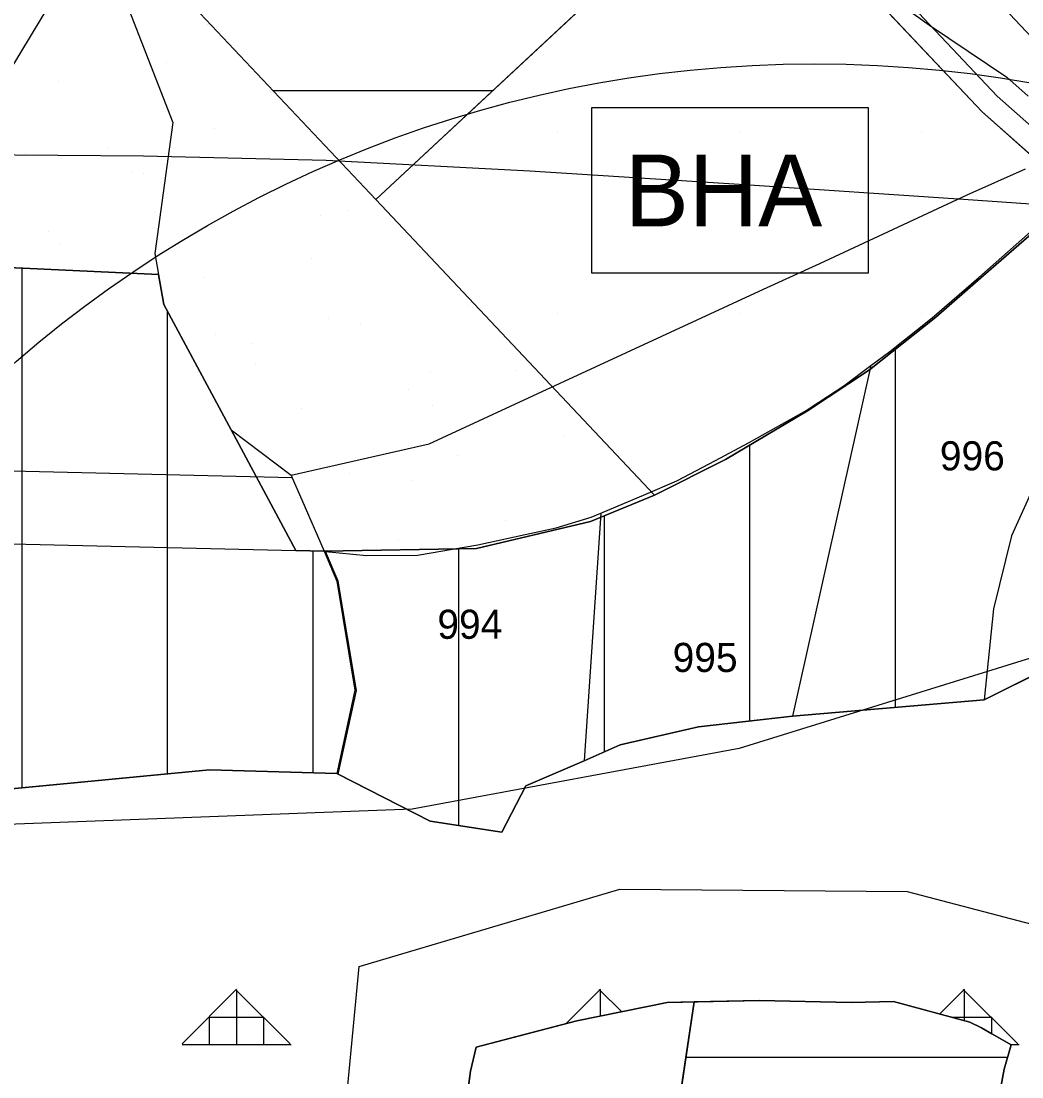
# Model space of a CAD drawing. Extents: x 410727 to 412947, y 4463506 to 4466382.
# Drawn here: x 411364.1 to 411501.6, y 4465781.8 to 4465926.9 of the extents above; entities that cross this region are included whole.
import ezdxf

# ---------------------------------------------------------------- set-up
doc = ezdxf.new("R2010")
doc.units = 0
for name, color, linetype in [('ADAKENARI', 7, 'Continuous'), ('KALDIRIM', 7, 'Continuous'), ('KDS_PARSEL_NO', 7, 'Continuous'), ('KDS_PL', 7, 'Continuous'), ('LJ_ÇERÇEVE', 7, 'Continuous'), ('PL_AYA_ORMAN', 7, 'Continuous'), ('PL_AYA_PARK_DINLENME', 7, 'Continuous'), ('PL_GELİŞME_KONUT', 7, 'Continuous'), ('PL_K_BHA', 7, 'Continuous'), ('PL_KON_MEV_050', 7, 'Continuous'), ('PL_KON_ONE_50', 7, 'Continuous'), ('sembol', 7, 'Continuous'), ('SN_ONAMA', 7, 'Continuous'), ('TR_AZYOGUNLUK_MESKUN', 7, 'Continuous'), ('TR_GELİŞME_KONUT_ÇOKAZ', 7, 'Continuous'), ('TR_ORMAN', 7, 'Continuous'), ('TR_PARKALANI', 7, 'Continuous'), ('TR_SU_DEPOSU', 7, 'Continuous'), ('Yerlesime_uygunluk_sınırı', 7, 'Continuous')]:
    doc.layers.add(name, color=color, linetype=linetype)

msp = doc.modelspace()

# ---------------------------------------------------------------- linework, layer by layer
at = {"layer": 'ADAKENARI'}
for p, q in [((411412.85, 4465902.41), (411463.26, 4465949.34)), ((411463.26, 4465949.34), (411496.15, 4465914.44)), ((411496.15, 4465914.44), (411508.68, 4465903.34)), ((411451.16, 4465861.77), (411412.85, 4465902.41)), ((411496.33, 4465891.98), (411503.64, 4465898.27)), ((411309.34, 4465895.53), (411383, 4465892.12)), ((411383, 4465892.12), (411383.75, 4465887.97)), ((411489.78, 4465886.25), (411496.33, 4465891.98)), ((411383.75, 4465887.97), (411393, 4465870.75)), ((411480.69, 4465879.01), (411489.78, 4465886.25)), ((411472.17, 4465873.35), (411480.69, 4465879.01)), ((411460.91, 4465866.67), (411472.17, 4465873.35)), ((411393, 4465870.75), (411401.9, 4465854.15)), ((411451.16, 4465861.77), (411460.91, 4465866.67)), ((411451.16, 4465861.77), (411442.37, 4465858.17)), ((411426.7, 4465854.46), (411442.37, 4465858.17)), ((411405.75, 4465854.06), (411401.9, 4465854.15)), ((411405.75, 4465854.06), (411426.7, 4465854.46)), ((411496.44, 4465833.66), (411538.79, 4465854.78)), ((411496.44, 4465833.66), (411470.13, 4465831.39)), ((411470.13, 4465831.39), (411457.2, 4465829.93)), ((411457.2, 4465829.93), (411446.43, 4465827.44)), ((411446.43, 4465827.44), (411441.48, 4465825.25)), ((411441.48, 4465825.25), (411433.46, 4465821.81)), ((411337.5, 4465818.97), (411390, 4465824)), ((411390, 4465824), (411407.51, 4465823.5)), ((411420.35, 4465816.97), (411407.51, 4465823.5)), ((411433.46, 4465821.81), (411430.18, 4465815.46)), ((411430.18, 4465815.46), (411420.35, 4465816.97)), ((411456.62, 4465792.14), (411445.98, 4465721.04))]:
    msp.add_line(p, q, dxfattribs=at)
for points in [[(411325.67, 4466003.81), (411366.7, 4465995.24), (411399.69, 4465991.77), (411415.6, 4465986.82), (411440.85, 4465973.12), (411463.26, 4465949.34), (411412.85, 4465902.41), (411380.18, 4465937.08), (411373.01, 4465940.76), (411281.5, 4465952.98)], [(411281.5, 4465952.98), (411373.01, 4465940.76), (411380.18, 4465937.08), (411412.85, 4465902.41), (411451.16, 4465861.77), (411442.37, 4465858.17), (411426.7, 4465854.46), (411405.75, 4465854.06), (411401.9, 4465854.15), (411393, 4465870.75), (411383.75, 4465887.97), (411383, 4465892.12), (411309.34, 4465895.53)], [(411424.6, 4465772.83), (411425.86, 4465782.59), (411426.64, 4465785.89), (411433.96, 4465787.81), (411440.46, 4465789.51), (411452.87, 4465792.03), (411465.59, 4465792.34), (411478.16, 4465792.03), (411483.97, 4465792.19), (411494.49, 4465789.35), (411496.06, 4465788.57), (411497.5, 4465787.74), (411500.15, 4465786.21), (411499.2, 4465782.9), (411498.42, 4465778.65)]]:
    msp.add_lwpolyline(points, dxfattribs=at)
at = {"layer": 'KALDIRIM'}
for points in [[(411363.84, 4466008.09), (411368.56, 4466007.11), (411402.12, 4466003.58), (411420.29, 4465997.93), (411448.26, 4465982.75), (411504.51, 4465923.06), (411515.54, 4465913.29), (411544.92, 4465897.92), (411576.35, 4465881.49), (411596.27, 4465871.64)], [(411592.71, 4465863.36), (411572.27, 4465873.46), (411540.75, 4465889.95), (411510.4, 4465905.83), (411498.24, 4465916.59), (411442.7, 4465975.53), (411416.77, 4465989.6), (411400.3, 4465994.72)]]:
    msp.add_lwpolyline(points, dxfattribs=at)
at = {"layer": 'KDS_PL'}
for p, q in [((411362.5, 4465919.97), (411374.5, 4465940)), ((411374.5, 4465940), (411385, 4465913)), ((411480.94, 4465932.11), (411488.93, 4465926.36)), ((411488.93, 4465926.36), (411499.54, 4465919.22)), ((411499.54, 4465919.22), (411502.49, 4465916.61)), ((411385, 4465913), (411382.5, 4465895)), ((411494.1, 4465903.04), (411502.12, 4465906.61)), ((411473.88, 4465893.63), (411494.1, 4465903.04)), ((411495.72, 4465891.7), (411502.79, 4465897.97)), ((411309.34, 4465895.53), (411383, 4465892.12)), ((411382.5, 4465895), (411383, 4465892.12)), ((411466.13, 4465890.07), (411473.88, 4465893.63)), ((411383, 4465892.12), (411383.75, 4465887.97)), ((411489.28, 4465886.15), (411495.72, 4465891.7)), ((411438.21, 4465877.16), (411466.13, 4465890.07)), ((411383.75, 4465887.97), (411393, 4465870.75)), ((411483.49, 4465881.52), (411489.28, 4465886.15)), ((411480.89, 4465879.59), (411483.49, 4465881.52)), ((411480.89, 4465879.59), (411470.13, 4465831.39)), ((411477.16, 4465876.8), (411480.89, 4465879.59)), ((411420.21, 4465868.83), (411438.21, 4465877.16)), ((411472.68, 4465873.85), (411477.16, 4465876.8)), ((411472.07, 4465873.44), (411472.68, 4465873.85)), ((411464.06, 4465868.96), (411472.07, 4465873.44)), ((411393, 4465870.75), (411401.25, 4465864.5)), ((411401.25, 4465864.5), (411420.21, 4465868.83)), ((411459.53, 4465866.52), (411464.06, 4465868.96)), ((411454.2, 4465863.75), (411459.53, 4465866.52)), ((411401.38, 4465864.16), (411343.25, 4465865.53)), ((411401.25, 4465864.5), (411401.38, 4465864.16)), ((411401.38, 4465864.16), (411402.69, 4465861.12)), ((411449.97, 4465861.89), (411454.2, 4465863.75)), ((411503.89, 4465864.4), (411500.21, 4465856.16)), ((411402.69, 4465861.12), (411405.75, 4465854.06)), ((411443.78, 4465859.29), (411449.97, 4465861.89)), ((411443.79, 4465859.3), (411441.49, 4465825.25)), ((411442.43, 4465858.73), (411443.79, 4465859.3)), ((411437.66, 4465857.29), (411442.43, 4465858.73)), ((411433.4, 4465856.35), (411437.66, 4465857.29)), ((411342.62, 4465855.53), (411405.75, 4465854.06)), ((411418.61, 4465853.53), (411426.88, 4465854.93)), ((411426.88, 4465854.93), (411433.4, 4465856.35)), ((411500.21, 4465856.16), (411497.7, 4465846.17)), ((411405.75, 4465854.06), (411407.5, 4465849.97)), ((411405.94, 4465854.02), (411411.57, 4465853.47)), ((411407.7, 4465849.93), (411405.94, 4465854.02)), ((411411.57, 4465853.47), (411418.61, 4465853.53)), ((411538.79, 4465854.78), (411496.44, 4465833.66)), ((411407.5, 4465849.97), (411410, 4465834.97)), ((411410.19, 4465834.91), (411407.7, 4465849.93)), ((411497.7, 4465846.17), (411496.44, 4465833.66)), ((411410, 4465834.97), (411407.5, 4465823.5)), ((411407.69, 4465823.41), (411410.19, 4465834.91)), ((411496.44, 4465833.66), (411470.13, 4465831.39)), ((411470.13, 4465831.39), (411457.2, 4465829.93)), ((411457.2, 4465829.93), (411446.43, 4465827.44)), ((411446.43, 4465827.44), (411441.48, 4465825.25)), ((411441.49, 4465825.25), (411439.18, 4465824.23)), ((411390, 4465824), (411337.5, 4465818.97)), ((411407.5, 4465823.5), (411390, 4465824)), ((411420.35, 4465816.97), (411407.69, 4465823.41)), ((411439.18, 4465824.23), (411433.46, 4465821.81)), ((411433.46, 4465821.81), (411430.18, 4465815.46)), ((411430.18, 4465815.46), (411420.35, 4465816.97)), ((411440.46, 4465789.51), (411452.87, 4465792.03)), ((411452.87, 4465792.03), (411465.59, 4465792.34)), ((411465.59, 4465792.34), (411478.16, 4465792.03)), ((411483.97, 4465792.19), (411478.16, 4465792.03)), ((411494.49, 4465789.35), (411483.97, 4465792.19)), ((411426.64, 4465785.89), (411440.46, 4465789.51)), ((411496.06, 4465788.57), (411494.49, 4465789.35)), ((411500.15, 4465786.21), (411496.06, 4465788.57)), ((411425.86, 4465782.59), (411426.64, 4465785.89)), ((411499.2, 4465782.9), (411500.15, 4465786.21)), ((411424.6, 4465772.83), (411425.86, 4465782.59)), ((411498.42, 4465778.65), (411499.2, 4465782.9))]:
    msp.add_line(p, q, dxfattribs=at)
at = {"layer": 'LJ_ÇERÇEVE'}
msp.add_circle((411473.17, 4465753.45), 167.6, dxfattribs=at)
at = {"layer": 'PL_AYA_ORMAN'}
for points in [[(411598.22, 4465856.51), (411570.91, 4465870.79), (411538.79, 4465854.78), (411496.44, 4465833.66), (411470.13, 4465831.39), (411457.2, 4465829.93), (411446.43, 4465827.44), (411441.48, 4465825.25), (411433.46, 4465821.81), (411430.18, 4465815.46), (411420.35, 4465816.97), (411407.51, 4465823.5), (411390, 4465824), (411337.5, 4465818.97)], [(411424.6, 4465772.83), (411425.86, 4465782.59), (411426.64, 4465785.89), (411440.46, 4465789.51), (411452.87, 4465792.03), (411465.59, 4465792.34), (411478.16, 4465792.03), (411483.97, 4465792.19), (411494.49, 4465789.35), (411496.06, 4465788.57), (411500.15, 4465786.21), (411499.2, 4465782.9), (411498.42, 4465778.65)]]:
    msp.add_lwpolyline(points, dxfattribs=at)
at = {"layer": 'PL_AYA_PARK_DINLENME'}
msp.add_lwpolyline([(411309.34, 4465895.53), (411383, 4465892.12), (411383.75, 4465887.97), (411393, 4465870.75), (411401.9, 4465854.15), (411405.75, 4465854.06), (411426.7, 4465854.46), (411442.37, 4465858.17), (411451.16, 4465861.77), (411412.85, 4465902.41), (411380.18, 4465937.08), (411373.01, 4465940.76), (411281.5, 4465952.98)], dxfattribs=at)
at = {"layer": 'PL_GELİŞME_KONUT'}
msp.add_lwpolyline([(411454.07, 4465719.35), (411454.07, 4465719.35), (411487.47, 4465711.77), (411488.52, 4465720.11), (411493.07, 4465740.04), (411493.07, 4465740.06), (411493.08, 4465740.1), (411496.22, 4465754.58), (411496.85, 4465761.03), (411497.95, 4465772.2), (411498.42, 4465778.65), (411499.2, 4465782.9), (411500.15, 4465786.21), (411497.5, 4465787.74), (411496.06, 4465788.57), (411494.49, 4465789.35), (411483.97, 4465792.19), (411478.16, 4465792.03), (411465.59, 4465792.34), (411456.62, 4465792.12), (411445.98, 4465721.04), (411445.98, 4465721.04)], dxfattribs=at)
at = {"layer": 'PL_K_BHA'}
for points in [[(411412.85, 4465902.41), (411451.16, 4465861.77), (411460.91, 4465866.67), (411472.17, 4465873.35), (411480.69, 4465879.01), (411489.78, 4465886.25), (411496.33, 4465891.98), (411503.64, 4465898.27), (411508.68, 4465903.34), (411496.15, 4465914.44), (411463.26, 4465949.34), (411412.85, 4465902.41)], [(411445.98, 4465721.04), (411456.62, 4465792.12), (411452.87, 4465792.03), (411440.46, 4465789.51), (411433.96, 4465787.81), (411426.64, 4465785.89), (411425.86, 4465782.59), (411424.6, 4465772.83), (411423.19, 4465756.15), (411419.73, 4465742.46), (411416.28, 4465732.86), (411412.98, 4465728.93), (411410.34, 4465725.3), (411410.34, 4465725.3)]]:
    msp.add_lwpolyline(points, dxfattribs=at)
at = {"layer": 'PL_KON_MEV_050'}
for points in [[(411503.64, 4465898.27), (411496.33, 4465891.98), (411489.78, 4465886.25), (411480.69, 4465879.01), (411472.17, 4465873.35), (411460.91, 4465866.67), (411451.16, 4465861.77), (411442.37, 4465858.17), (411426.7, 4465854.46), (411405.75, 4465854.06), (411401.9, 4465854.15), (411393, 4465870.75), (411383.75, 4465887.97), (411383, 4465892.12), (411309.34, 4465895.53)], [(411337.5, 4465818.97), (411390, 4465824), (411407.51, 4465823.5), (411420.35, 4465816.97), (411430.18, 4465815.46), (411433.46, 4465821.81), (411441.48, 4465825.25), (411446.43, 4465827.44), (411457.2, 4465829.93), (411470.13, 4465831.39), (411496.44, 4465833.66), (411538.79, 4465854.78)]]:
    msp.add_lwpolyline(points, dxfattribs=at)
at = {"layer": 'PL_KON_ONE_50'}
msp.add_lwpolyline([(411281.5, 4465952.98), (411373.01, 4465940.76), (411380.18, 4465937.08), (411412.85, 4465902.41), (411463.26, 4465949.34), (411440.85, 4465973.12), (411415.6, 4465986.82), (411399.69, 4465991.77), (411366.7, 4465995.24), (411325.67, 4466003.81)], dxfattribs=at)
at = {"layer": 'sembol'}
for p, q in [((411442.55, 4465892.27), (411442.55, 4465915.05)), ((411442.55, 4465915.05), (411480.51, 4465915.05)), ((411480.51, 4465915.05), (411480.51, 4465892.27)), ((411480.51, 4465892.27), (411442.55, 4465892.27))]:
    msp.add_line(p, q, dxfattribs=at)
at = {"layer": 'SN_ONAMA'}
msp.add_lwpolyline([(411383.47, 4465701.98), (411406.89, 4465758.05), (411410.6, 4465797.01), (411446.38, 4465807.63), (411485.88, 4465807.28), (411522.02, 4465797.82), (411500.54, 4465684.33), (411414.88, 4465701.98)], close=True, dxfattribs=at)
at = {"layer": 'TR_AZYOGUNLUK_MESKUN'}
for p, q in [((411364.26, 4465821.53), (411364.26, 4465892.99)), ((411384.26, 4465823.45), (411384.26, 4465887.02)), ((411484.26, 4465832.61), (411484.26, 4465881.85)), ((411464.26, 4465830.73), (411464.26, 4465868.66)), ((411444.26, 4465826.48), (411444.26, 4465858.94)), ((411404.26, 4465823.59), (411404.26, 4465854.09)), ((411424.26, 4465816.37), (411424.26, 4465854.41))]:
    msp.add_line(p, q, dxfattribs=at)
at = {"layer": 'TR_GELİŞME_KONUT_ÇOKAZ'}
for p, q in [((411398.74, 4465917.39), (411428.94, 4465917.39)), ((411455.49, 4465784.54), (411499.51, 4465784.54))]:
    msp.add_line(p, q, dxfattribs=at)
msp.add_lwpolyline([(411281.5, 4465952.98), (411373.01, 4465940.76), (411380.18, 4465937.08), (411412.85, 4465902.41), (411463.26, 4465949.34), (411440.85, 4465973.12), (411415.6, 4465986.82), (411399.69, 4465991.77), (411366.7, 4465995.24), (411325.67, 4466003.81)], dxfattribs=at)
at = {"layer": 'TR_ORMAN'}
for p, q in [((411386.24, 4465786.37), (411393.74, 4465793.87)), ((411401.08, 4465786.34), (411393.58, 4465793.84)), ((411393.75, 4465786.29), (411393.75, 4465793.79)), ((411438.99, 4465789.12), (411443.74, 4465793.88)), ((411446.65, 4465790.77), (411443.57, 4465793.84)), ((411443.75, 4465790.18), (411443.75, 4465793.79)), ((411490.33, 4465790.47), (411493.74, 4465793.89)), ((411501.07, 4465786.34), (411493.57, 4465793.84)), ((411493.75, 4465789.55), (411493.75, 4465793.79)), ((411390, 4465786.29), (411390, 4465790.04)), ((411390, 4465790.04), (411397.5, 4465790.04)), ((411397.5, 4465786.29), (411397.5, 4465790.04)), ((411491.94, 4465790.04), (411497.5, 4465790.04)), ((411497.5, 4465787.74), (411497.5, 4465790.04)), ((411386.25, 4465786.29), (411401.25, 4465786.29)), ((411500, 4465786.29), (411501.25, 4465786.29))]:
    msp.add_line(p, q, dxfattribs=at)
at = {"layer": 'TR_PARKALANI'}
for p, q in [((411389.78, 4465926.43), (411389.78, 4465926.43)), ((411389.78, 4465926.43), (411389.78, 4465926.43)), ((411384.07, 4465921.17), (411384.07, 4465921.17)), ((411384.07, 4465921.17), (411384.07, 4465921.17)), ((411369.3, 4465918.57), (411369.3, 4465918.57)), ((411369.3, 4465918.57), (411369.3, 4465918.57)), ((411390.73, 4465912.19), (411390.73, 4465912.19)), ((411390.73, 4465912.19), (411390.73, 4465912.19)), ((411364.71, 4465908.71), (411364.71, 4465908.71)), ((411375.96, 4465909.59), (411375.96, 4465909.59)), ((411375.96, 4465909.59), (411375.96, 4465909.59)), ((411395.13, 4465908.42), (411395.13, 4465908.42)), ((411379.48, 4465906.1), (411379.48, 4465906.1)), ((411380.89, 4465905.92), (411380.89, 4465905.92)), ((411397.39, 4465903.21), (411397.39, 4465903.21)), ((411397.39, 4465903.21), (411397.39, 4465903.21)), ((411382.62, 4465900.61), (411382.62, 4465900.61)), ((411382.62, 4465900.61), (411382.62, 4465900.61)), ((411405.23, 4465900.24), (411405.23, 4465900.24)), ((411405.23, 4465900.24), (411405.23, 4465900.24)), ((411409.03, 4465900.89), (411409.03, 4465900.89)), ((411367.85, 4465898), (411367.85, 4465898)), ((411367.85, 4465898), (411367.85, 4465898)), ((411369.4, 4465896.28), (411369.4, 4465896.28)), ((411369.4, 4465896.28), (411369.4, 4465896.28)), ((411404.05, 4465894.23), (411404.05, 4465894.23)), ((411404.05, 4465894.23), (411404.05, 4465894.23)), ((411389.28, 4465891.63), (411389.28, 4465891.63)), ((411389.28, 4465891.63), (411389.28, 4465891.63)), ((411425.49, 4465887.86), (411425.49, 4465887.86)), ((411425.49, 4465887.86), (411425.49, 4465887.86)), ((411406.42, 4465886.12), (411406.42, 4465886.12)), ((411410.71, 4465885.25), (411410.71, 4465885.25)), ((411410.71, 4465885.25), (411410.71, 4465885.25)), ((411390.78, 4465883.8), (411390.78, 4465883.8)), ((411395.94, 4465882.65), (411395.94, 4465882.65)), ((411395.94, 4465882.65), (411395.94, 4465882.65)), ((411396.34, 4465879.72), (411396.34, 4465879.72)), ((411420.33, 4465878.59), (411420.33, 4465878.59)), ((411432.15, 4465878.88), (411432.15, 4465878.88)), ((411432.15, 4465878.88), (411432.15, 4465878.88)), ((411417.38, 4465876.27), (411417.38, 4465876.27)), ((411417.38, 4465876.27), (411417.38, 4465876.27)), ((411435.1, 4465875.99), (411435.1, 4465875.99)), ((411420.69, 4465874.04), (411420.69, 4465874.04)), ((411420.69, 4465874.04), (411420.69, 4465874.04)), ((411402.6, 4465873.67), (411402.6, 4465873.67)), ((411402.6, 4465873.67), (411402.6, 4465873.67)), ((411438.81, 4465869.9), (411438.81, 4465869.9)), ((411438.81, 4465869.9), (411438.81, 4465869.9)), ((411424.04, 4465867.29), (411424.04, 4465867.29)), ((411424.04, 4465867.29), (411424.04, 4465867.29)), ((411409.26, 4465864.69), (411409.26, 4465864.69)), ((411409.26, 4465864.69), (411409.26, 4465864.69)), ((411417.72, 4465863.82), (411417.72, 4465863.82)), ((411402.08, 4465861.5), (411402.08, 4465861.5)), ((411445.47, 4465860.92), (411445.47, 4465860.92)), ((411445.47, 4465860.92), (411445.47, 4465860.92)), ((411430.7, 4465858.31), (411430.7, 4465858.31)), ((411430.7, 4465858.31), (411430.7, 4465858.31)), ((411415.92, 4465855.71), (411415.92, 4465855.71)), ((411415.92, 4465855.71), (411415.92, 4465855.71)), ((411431.63, 4465856.29), (411431.63, 4465856.29))]:
    msp.add_line(p, q, dxfattribs=at)
at = {"layer": 'TR_SU_DEPOSU'}
for p, q in [((411437.85, 4465911.77), (411437.85, 4465911.77)), ((411462.85, 4465911.77), (411462.85, 4465911.77)), ((411487.85, 4465911.77), (411487.85, 4465911.77)), ((411437.85, 4465886.77), (411437.85, 4465886.77)), ((411462.85, 4465886.77), (411462.85, 4465886.77)), ((411487.85, 4465886.77), (411487.85, 4465886.77))]:
    msp.add_line(p, q, dxfattribs=at)
at = {"layer": 'Yerlesime_uygunluk_sınırı'}
for points in [[(411367.59, 4466324.54), (411367.57, 4466324.45), (411365.4, 4466317.37), (411329.85, 4466256.4), (411327.98, 4466256.94), (411298.02, 4466265.64), (411235.39, 4466203.01), (411292.89, 4466117.8), (411249.96, 4466080.27), (411288.76, 4466053.15), (411335.49, 4466003.87), (411401.49, 4466010.55), (411454, 4465988), (411518.19, 4465927.25), (411576.49, 4465880.17), (411546.8, 4465853.02), (411462.76, 4465826.95), (411417.87, 4465818.6), (411360.95, 4465816.44), (411257.66, 4465822.32), (411198.74, 4465810.19), (411081.53, 4465694.24)], [(411554.2, 4465898.16), (411523.87, 4465900.28), (411493.6, 4465902.39), (411463.53, 4465904.43), (411434.03, 4465906.31), (411406.06, 4465907.75), (411380.94, 4465908.37), (411357.39, 4465908.53)]]:
    msp.add_lwpolyline(points, dxfattribs=at)

# ---------------------------------------------------------------- texts
at = {"layer": 'KDS_PARSEL_NO'}
for s, p in [('996', (411490.35, 4465865.18)), ('994', (411421.32, 4465842.03)), ('995', (411453.64, 4465837.47))]:
    msp.add_text(s, height=4, dxfattribs=at).set_placement(p)
at = {"layer": 'sembol'}
msp.add_text('BHA', height=9.869, dxfattribs=at).set_placement((411447.06, 4465898.72))

doc.saveas('drawing.dxf')
